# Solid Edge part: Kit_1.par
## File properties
Sűrűség: 0,000 kg/m^3
Pontosság: 0,990
Author: ahadarics
Last saved by: psaghy
Revision: 78
Username: ahadarics
Dokumentum tartalom típus: 0
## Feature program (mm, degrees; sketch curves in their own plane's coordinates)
base feature "unnamed BaseFeature 1"
sketch for "Furat_1" plane through (0, 0, 48.5) normal (0, 0, 1) x-axis (0.707107, -0.707107, 0)
  hole centre (-62.9325, 0) bore radius 4.188
hole "Furat_1" nominal diameter 10 finite  VBottomAngle = 118 deg
sketch for "unnamed Hole 1" plane through (0, 0, 48.5) normal (0, 0, 1) x-axis (0.707107, -0.707107, 0)
  hole centre (0, 62.9325) bore radius 4.188
hole "unnamed Hole 1" finite
sketch for "unnamed Hole 2" plane through (0, 0, 48.5) normal (0, 0, 1) x-axis (0.707107, -0.707107, 0)
  hole centre (62.9325, 0) bore radius 4.188
hole "unnamed Hole 2" finite
sketch for "unnamed Hole 3" plane through (0, 0, 48.5) normal (0, 0, 1) x-axis (0.707107, -0.707107, 0)
  hole centre (0, -62.9325) bore radius 4.188
hole "unnamed Hole 3" finite
pattern "unnamed Pattern 1" of "Furat_1", "unnamed Hole 1", "unnamed Hole 2", "unnamed Hole 3"
sketch for "Furat_5" plane through (55, -0.0046, 26.9988) normal (1, 0, 0) x-axis (0, 0, 1)
hole "Furat_5" diameter 20.955 finite  ThreadDepth = 25 mm
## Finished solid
Body 1: solid body, 519 faces, 1182 edges, 718 vertices, 6 internal voids.
  Faces by surface: cylinder 169, plane 151, sphere 54, cone 52, torus 47, spline 28, swept 18
  Edges by curve: curve on surface 410, circle 372, line 356, spline 40, ellipse 4
Bounding box of the edges (mm; curved faces can reach further): 110.000 x 110.000 x 44.500, from (-55, -55, 8) to (55, 55, 52.5).
Cylindrical faces by radius (mm): R0.3906 x2, R0.436 x1, R0.4566 x1, R0.5319 x1, R0.6854 x2, R0.701 x1, R0.7273 x1, R0.7952 x1, R0.8489 x1, R0.9223 x1, R1 x31, R1.0003 x1, R1.0017 x8, R1.1393 x1, R1.2532 x1, R1.2992 x1, R1.3173 x1, R1.3418 x1, R1.3734 x1, R1.4839 x1, R1.5702 x1, R1.5902 x3, R1.7026 x2, R1.7139 x2, R1.8341 x1, R2 x12, R2.0009 x12, R2.003 x12, R2.0038 x6, R2.0039 x6, R2.1429 x2, R2.1983 x1, R2.95 x1, R4.188 x8, R5 x4, R5.15 x4, R6 x2, R8 x4, R8.15 x4, R8.5 x2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
Conical faces (half-angle, radius in mm at the cone's reference point): 0.0014 deg R1.001 x6, 1 deg R24.75 x6, 1 deg R44 x6, 30 deg R6.1443 x1, 43.4089 deg R46.25 x1, 45 deg R3.75 x1, 45 deg R3.875 x1, 45 deg R5.3 x8, 45 deg R7.85 x8, 45 deg R10.91 x1, 47.9357 deg R39.7887 x6, 47.9357 deg R47.75 x3, 59 deg R4.188 x4
Toroidal faces (ring radius, tube radius in mm): R5.3 r0.3 x4, R5.7 r0.3 x1, R7.95 r0.2 x4, R8.65 r0.5 x4, R11.5 r1 x2, R15.5 r1 x1, R26.7154 r2 x6, R27 r0.5 x1, R28 r0.5 x1, R34.8084 r2 x6, R42.0155 r2 x6, R53 r1 x3, R55.4306 r1 x2, R57 r1 x6
Spherical faces by radius (mm): R1 x18, R2 x36
Planar faces by outward normal: +x 20, +y 11, +z 31, -x 1, -y 10, -z 21, oblique 57
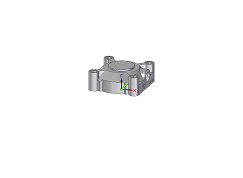
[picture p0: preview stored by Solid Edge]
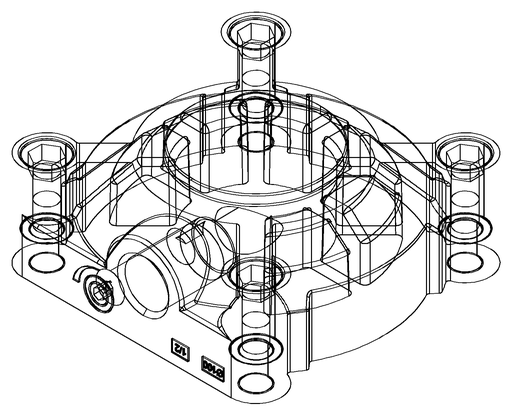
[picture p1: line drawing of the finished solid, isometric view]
